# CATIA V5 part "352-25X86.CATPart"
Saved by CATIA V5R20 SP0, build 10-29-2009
Part number: 352-25X86
Definition: NONE
Nomenclature: 352-25X86
Source: Unknown
Description: 352-25X86
Bounding box of the stored display mesh (mm): x 0 to 86, y -17 to 17, z -17 to 17
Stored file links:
  C:\Users\Utente\Desktop\IO LAVORO\3D X SITO CF\X SITO\PLASTICA\352\352-25X86.CATPart
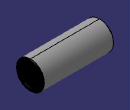
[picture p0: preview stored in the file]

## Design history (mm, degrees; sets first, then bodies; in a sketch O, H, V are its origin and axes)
Body1 "352-25X86" (main body)
  Solid1: solid without history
